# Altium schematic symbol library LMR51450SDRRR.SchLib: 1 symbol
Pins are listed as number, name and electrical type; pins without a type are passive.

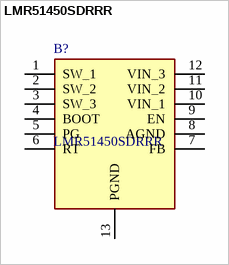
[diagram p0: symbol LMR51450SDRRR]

## LMR51450SDRRR
designator B?
Switching Voltage Regulators 36-V, 5-A synchronous buck converter; Manufacturer_Name: Texas Instruments; Geometry.Height: 0.8mm
footprint SON50P300X300X80-13N-D
pins: 1 SW_1, 2 SW_2, 3 SW_3, 4 BOOT, 5 PG, 6 RT, 7 FB, 8 AGND, 9 EN, 10 VIN_1, 11 VIN_2, 12 VIN_3, 13 PGND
